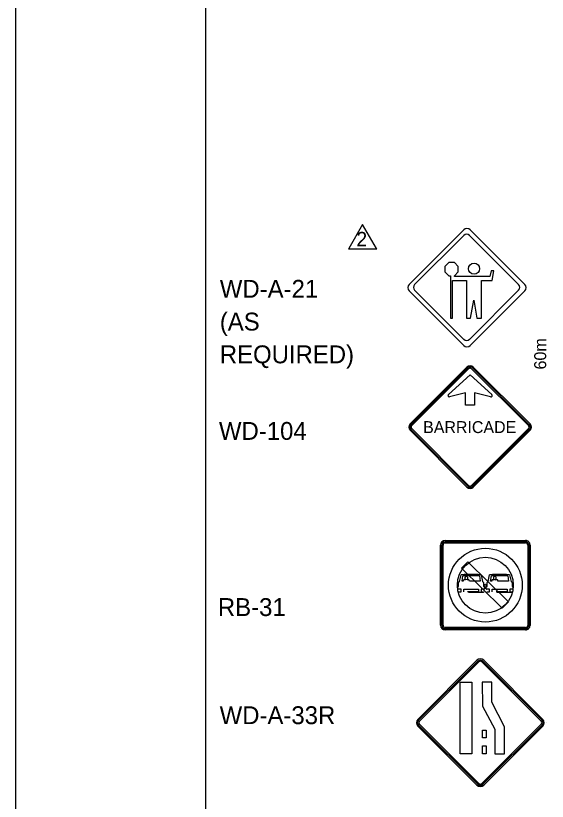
# Model space of a CAD drawing. Extents: x 1056 to 1280, y 240 to 519.
# Drawn here: x 1055.6 to 1109, y 308.9 to 388 of the extents above; entities that cross this region are included whole.
import ezdxf

# ---------------------------------------------------------------- set-up
doc = ezdxf.new("R2010")
doc.units = 0
for name, color, linetype in [('Level 1', 7, 'Continuous'), ('Level 10', 7, 'Continuous'), ('Level 17', 7, 'Continuous'), ('Level 29', 7, 'Continuous'), ('Level 44', 7, 'Continuous')]:
    doc.layers.add(name, color=color, linetype=linetype)

msp = doc.modelspace()

# ---------------------------------------------------------------- linework, layer by layer
at = {"layer": 'Level 1'}
for p, q in [((1099.137, 363.179), (1098.743, 362.785)), ((1099.694, 363.179), (1099.137, 363.179)), ((1100.088, 362.785), (1099.694, 363.179)), ((1098.743, 362.785), (1098.743, 362.228)), ((1100.088, 362.228), (1100.088, 362.785)), ((1103.408, 362.36), (1103.264, 361.761)), ((1103.658, 362.36), (1103.408, 362.36)), ((1103.495, 361.359), (1103.658, 362.36)), ((1098.743, 362.228), (1099.137, 361.834)), ((1099.137, 361.834), (1099.315, 361.834)), ((1099.315, 361.834), (1099.315, 357.568)), ((1099.694, 361.834), (1100.088, 362.228)), ((1099.694, 361.761), (1099.694, 361.834)), ((1103.264, 361.761), (1099.694, 361.761)), ((1099.511, 357.568), (1099.511, 361.359)), ((1099.511, 361.359), (1100.931, 361.359)), ((1100.931, 361.359), (1100.931, 357.568)), ((1102.419, 357.568), (1102.419, 361.359)), ((1102.419, 361.359), (1103.495, 361.359)), ((1101.307, 357.568), (1101.644, 359.384)), ((1101.644, 359.384), (1101.961, 357.568)), ((1099.315, 357.568), (1099.511, 357.568)), ((1100.931, 357.568), (1101.307, 357.568)), ((1101.961, 357.568), (1102.419, 357.568))]:
    msp.add_line(p, q, dxfattribs=at)
msp.add_circle((1101.68, 362.56), 0.559, dxfattribs=at)
at = {"layer": 'Level 10'}
for points in [[(1055.562, 518.817), (1271.562, 518.817), (1271.562, 239.817), (1055.562, 239.817)], [(1074.688, 508.008), (1261.562, 508.008), (1261.562, 250.626), (1074.688, 250.626)]]:
    msp.add_lwpolyline(points, close=True, dxfattribs=at)
at = {"layer": 'Level 17'}
for p, q in [((1095.234, 346.927), (1100.953, 352.646)), ((1095.319, 346.842), (1101.038, 352.562)), ((1095.404, 346.758), (1101.123, 352.477)), ((1101.428, 352.477), (1107.148, 346.758)), ((1101.513, 352.562), (1107.232, 346.842)), ((1101.598, 352.646), (1107.317, 346.927)), ((1099.212, 349.644), (1099.212, 349.644)), ((1099.212, 349.644), (1099.212, 349.644)), ((1099.212, 349.644), (1099.212, 349.644)), ((1094.912, 346.605), (1094.912, 346.605)), ((1100.953, 340.563), (1095.234, 346.282)), ((1101.038, 340.648), (1095.319, 346.367)), ((1101.123, 340.733), (1095.404, 346.452)), ((1107.148, 346.452), (1101.428, 340.733)), ((1107.232, 346.367), (1101.513, 340.648)), ((1107.317, 346.282), (1101.598, 340.563)), ((1098.311, 326.645), (1098.311, 334.724)), ((1098.431, 326.645), (1098.431, 334.724)), ((1098.551, 326.645), (1098.551, 334.724)), ((1098.768, 335.181), (1106.852, 335.185)), ((1098.768, 335.061), (1106.852, 335.065)), ((1098.768, 334.941), (1106.852, 334.946)), ((1107.07, 334.729), (1107.069, 326.639)), ((1107.19, 334.729), (1107.189, 326.639)), ((1107.31, 334.729), (1107.309, 326.639)), ((1100.226, 331.041), (1100.376, 331.723)), ((1100.468, 331.104), (1100.554, 331.627)), ((1100.593, 331.667), (1102.162, 331.667)), ((1102.209, 331.627), (1102.289, 331.104)), ((1102.381, 331.723), (1102.531, 331.041)), ((1103.092, 331.041), (1103.242, 331.723)), ((1103.334, 331.104), (1103.42, 331.627)), ((1103.459, 331.667), (1105.028, 331.667)), ((1105.074, 331.627), (1105.155, 331.104)), ((1105.247, 331.723), (1105.397, 331.041)), ((1100.124, 330.971), (1100.227, 331.041)), ((1100.124, 330.552), (1100.124, 330.971)), ((1100.582, 331.104), (1100.468, 331.104)), ((1100.589, 331.173), (1100.582, 331.104)), ((1100.808, 331.224), (1100.635, 331.213)), ((1100.819, 331.287), (1100.819, 331.235)), ((1100.969, 331.235), (1100.969, 331.287)), ((1101.158, 331.213), (1100.985, 331.224)), ((1101.208, 331.104), (1101.197, 331.173)), ((1102.289, 331.104), (1101.208, 331.104)), ((1102.531, 331.041), (1102.634, 330.971)), ((1102.634, 330.971), (1102.634, 330.552)), ((1102.99, 330.971), (1103.093, 331.041)), ((1102.99, 330.552), (1102.99, 330.971)), ((1103.448, 331.104), (1103.334, 331.104)), ((1103.454, 331.173), (1103.448, 331.104)), ((1103.674, 331.224), (1103.501, 331.213)), ((1103.684, 331.287), (1103.684, 331.235)), ((1103.834, 331.235), (1103.834, 331.287)), ((1104.023, 331.213), (1103.851, 331.224)), ((1104.074, 331.104), (1104.063, 331.173)), ((1105.155, 331.104), (1104.074, 331.104)), ((1105.397, 331.041), (1105.499, 330.971)), ((1105.499, 330.971), (1105.499, 330.552)), ((1100.033, 330.329), (1100.033, 330.506)), ((1100.079, 330.552), (1100.124, 330.552)), ((1100.366, 330.282), (1100.079, 330.282)), ((1100.142, 329.937), (1100.142, 330.012)), ((1100.142, 330.012), (1100.366, 330.012)), ((1100.366, 330.012), (1100.366, 330.282)), ((1100.631, 330.012), (1100.631, 330.282)), ((1100.631, 330.282), (1102.128, 330.282)), ((1102.128, 330.012), (1101.031, 330.012)), ((1102.616, 329.937), (1101.106, 329.937)), ((1102.128, 330.282), (1102.128, 330.012)), ((1102.679, 330.282), (1102.392, 330.282)), ((1102.392, 330.282), (1102.392, 330.012)), ((1102.392, 330.012), (1102.616, 330.012)), ((1102.616, 330.012), (1102.616, 329.937)), ((1102.634, 330.552), (1102.679, 330.552)), ((1102.725, 330.506), (1102.725, 330.329)), ((1102.898, 330.329), (1102.898, 330.506)), ((1102.945, 330.552), (1102.99, 330.552)), ((1103.232, 330.282), (1102.945, 330.282)), ((1103.007, 329.937), (1103.007, 330.012)), ((1103.007, 330.012), (1103.232, 330.012)), ((1103.232, 330.012), (1103.232, 330.282)), ((1103.496, 330.012), (1103.496, 330.282)), ((1103.496, 330.282), (1104.993, 330.282)), ((1104.993, 330.012), (1103.897, 330.012)), ((1105.482, 329.937), (1103.971, 329.937)), ((1104.993, 330.282), (1104.993, 330.012)), ((1105.545, 330.282), (1105.258, 330.282)), ((1105.258, 330.282), (1105.258, 330.012)), ((1105.258, 330.012), (1105.482, 330.012)), ((1105.482, 330.012), (1105.482, 329.937)), ((1105.499, 330.552), (1105.545, 330.552)), ((1105.591, 330.506), (1105.591, 330.329)), ((1098.311, 326.189), (1098.311, 326.189)), ((1098.311, 326.189), (1098.311, 326.189)), ((1106.853, 326.423), (1098.768, 326.428)), ((1106.853, 326.303), (1098.768, 326.308)), ((1106.853, 326.183), (1098.768, 326.188)), ((1096.012, 317.172), (1101.97, 323.13)), ((1096.101, 317.083), (1102.059, 323.041)), ((1096.19, 316.996), (1102.148, 322.952)), ((1102.465, 322.952), (1108.422, 316.996)), ((1102.554, 323.041), (1108.511, 317.083)), ((1102.642, 323.13), (1108.6, 317.172)), ((1101.97, 310.543), (1096.012, 316.501)), ((1102.059, 310.631), (1096.101, 316.588)), ((1102.148, 310.72), (1096.19, 316.677)), ((1108.422, 316.677), (1102.465, 310.72)), ((1108.511, 316.588), (1102.554, 310.631)), ((1108.6, 316.501), (1102.642, 310.543)), ((1108.935, 316.836), (1108.935, 316.836))]:
    msp.add_line(p, q, dxfattribs=at)
for points in [[(1099.089, 349.878), (1101.276, 351.866), (1103.463, 349.878)], [(1099.089, 349.878), (1101.276, 351.866), (1103.463, 349.878)], [(1099.089, 349.878), (1101.276, 351.866), (1103.463, 349.878)], [(1103.334, 349.644), (1101.727, 350.056), (1101.727, 348.806), (1100.82, 348.806), (1100.82, 350.056), (1099.212, 349.644)], [(1103.334, 349.644), (1101.727, 350.056), (1101.727, 348.806), (1100.82, 348.806), (1100.82, 350.056), (1099.212, 349.644)], [(1103.334, 349.644), (1101.727, 350.056), (1101.727, 348.806), (1100.82, 348.806), (1100.82, 350.056), (1099.212, 349.644)]]:
    msp.add_lwpolyline(points, dxfattribs=at)
for points in [[(1101.039, 333.029), (1105.138, 329.004), (1104.503, 328.368), (1100.405, 332.393)], [(1100.266, 320.928), (1101.438, 320.928), (1101.438, 313.688), (1100.266, 313.688)], [(1102.492, 320.928), (1102.508, 318.517), (1103.756, 316.193), (1103.756, 313.688), (1104.731, 313.688), (1104.731, 316.433), (1103.466, 318.907), (1103.466, 320.928)], [(1102.508, 316.098), (1102.898, 316.098), (1102.898, 315.296), (1102.508, 315.296)], [(1102.508, 314.492), (1102.898, 314.492), (1102.898, 313.688), (1102.508, 313.688)]]:
    msp.add_lwpolyline(points, close=True, dxfattribs=at)
for radius in [3.715, 2.811, 0.109]:
    msp.add_circle((1102.812, 330.685), radius, dxfattribs=at)
for centre, radius, start, end in [((1101.276, 352.323), 0.456, 45, 135), ((1101.276, 352.323), 0.336, 45, 135), ((1101.276, 352.323), 0.216, 45, 135), ((1099.18, 349.774), 0.137, 132.30479, 284.40748), ((1099.18, 349.774), 0.137, 132.30479, 284.40748), ((1099.18, 349.774), 0.137, 132.30479, 284.40748), ((1103.369, 349.774), 0.137, 255.59252, 47.69521), ((1103.369, 349.774), 0.137, 255.59252, 47.69521), ((1103.369, 349.774), 0.137, 255.59252, 47.69521), ((1095.557, 346.604), 0.456, 135, 225), ((1095.557, 346.604), 0.336, 135, 225), ((1095.557, 346.604), 0.216, 135, 225), ((1106.995, 346.604), 0.216, 315, 45), ((1106.995, 346.604), 0.336, 315, 45), ((1106.995, 346.604), 0.456, 315, 45), ((1101.276, 340.885), 0.456, 225, 315), ((1101.276, 340.885), 0.336, 225, 315), ((1101.276, 340.885), 0.216, 225, 315), ((1098.769, 334.724), 0.457, 90.03529, 179.99948), ((1098.769, 334.724), 0.337, 90.03529, 179.99948), ((1098.769, 334.724), 0.217, 90.03529, 179.99948), ((1106.853, 334.729), 0.457, 0, 90.03486), ((1106.853, 334.729), 0.337, 0, 90.03486), ((1106.853, 334.729), 0.217, 0, 90.03486), ((1100.596, 331.62), 0.0448, 90, 170.90972), ((1100.897, 331.424), 0.149, 302.76657, 235.94147), ((1102.163, 331.62), 0.0448, 9.09028, 90), ((1103.462, 331.62), 0.0448, 90, 170.90972), ((1103.763, 331.424), 0.149, 302.76657, 235.94147), ((1105.029, 331.62), 0.0448, 9.09028, 90), ((1100.636, 331.167), 0.0448, 93.82218, 171.86989), ((1100.806, 331.238), 0.0149, 273.79849, 0), ((1100.806, 331.287), 0.015, 0, 60.10537), ((1100.985, 331.285), 0.0149, 119.13929, 180), ((1100.985, 331.238), 0.0149, 180, 266.20151), ((1101.155, 331.167), 0.0448, 8.11866, 86.21836), ((1103.502, 331.167), 0.0448, 93.82218, 171.86989), ((1103.672, 331.238), 0.0149, 273.79849, 0), ((1103.672, 331.287), 0.015, 0, 60.10537), ((1103.851, 331.285), 0.0149, 119.13929, 180), ((1103.851, 331.238), 0.0149, 180, 266.20151), ((1104.021, 331.167), 0.0448, 8.11866, 86.21836), ((1100.08, 330.508), 0.0448, 90.00001, 180.00001), ((1100.08, 330.328), 0.0448, 180.00001, 270), ((1102.679, 330.508), 0.0448, 359.99999, 89.99999), ((1102.679, 330.328), 0.0448, 270, 359.99999), ((1102.946, 330.508), 0.0448, 90.00001, 180.00001), ((1102.946, 330.328), 0.0448, 180.00001, 270), ((1105.545, 330.508), 0.0448, 359.99999, 89.99999), ((1105.545, 330.328), 0.0448, 270, 359.99999), ((1098.769, 326.645), 0.457, 180, 269.96489), ((1098.769, 326.645), 0.337, 180, 269.96489), ((1098.769, 326.645), 0.217, 180, 269.96489), ((1106.853, 326.64), 0.457, 269.96512, 0), ((1106.853, 326.64), 0.337, 269.96512, 0), ((1106.853, 326.64), 0.217, 269.96512, 0), ((1102.306, 322.793), 0.475, 45, 135), ((1102.306, 322.793), 0.35, 45, 135), ((1102.306, 322.793), 0.225, 45, 135), ((1096.348, 316.836), 0.475, 135, 225), ((1096.348, 316.836), 0.35, 135, 225), ((1096.348, 316.836), 0.225, 135, 225), ((1108.263, 316.836), 0.225, 315, 45), ((1108.263, 316.836), 0.35, 315, 45), ((1108.263, 316.836), 0.475, 315, 45), ((1102.306, 310.879), 0.475, 225, 315), ((1102.306, 310.879), 0.35, 225, 315), ((1102.306, 310.879), 0.225, 225, 315)]:
    msp.add_arc(centre, radius, start, end, dxfattribs=at)
for centre in [(1101.38, 331.725), (1104.245, 331.725)]:
    msp.add_ellipse(centre, major_axis=(-1.001, 0), ratio=0.04642, start_param=3.141593, end_param=6.283185, dxfattribs=at)
at = {"layer": 'Level 29'}
for points in [[(1090.467, 367.02), (1089.074, 364.595)], [(1091.861, 364.595), (1090.467, 367.02)], [(1089.074, 364.595), (1089.048, 364.55), (1091.887, 364.55), (1091.861, 364.595)]]:
    msp.add_lwpolyline(points, dxfattribs=at)
at = {"layer": 'Level 44'}
for p, q in [((1100.638, 366.462), (1095.144, 360.976)), ((1106.772, 360.976), (1101.288, 366.462)), ((1095.694, 360.972), (1100.638, 365.91)), ((1101.222, 365.91), (1106.16, 360.972)), ((1095.144, 360.326), (1100.638, 354.834)), ((1095.15, 360.326), (1095.144, 360.326)), ((1100.638, 355.446), (1095.694, 360.386)), ((1106.16, 360.386), (1101.222, 355.446)), ((1101.288, 354.834), (1106.772, 360.326))]:
    msp.add_line(p, q, dxfattribs=at)
for centre, radius, start, end in [((1100.962, 366.139), 0.459, 45, 135), ((1100.929, 365.618), 0.413, 45, 135), ((1095.473, 360.65), 0.459, 135, 224.99999), ((1095.99, 360.678), 0.413, 135, 224.99999), ((1105.869, 360.678), 0.413, 315, 45), ((1106.45, 360.65), 0.459, 315, 45), ((1100.929, 355.739), 0.413, 225, 315), ((1100.962, 355.162), 0.459, 225, 315)]:
    msp.add_arc(centre, radius, start, end, dxfattribs=at)

# ---------------------------------------------------------------- texts
at = {"layer": 'Level 10'}
msp.add_text('2', height=1.448, rotation=360, dxfattribs=at).set_placement((1089.84, 364.819))
for s, p in [('WD-A-21', (1076.095, 359.634)), ('WD-A-21', (1076.095, 359.634)), ('(AS ', (1076.095, 356.334)), ('(AS ', (1076.095, 356.334)), ('REQUIRED)', (1076.095, 353.034)), ('REQUIRED)', (1076.095, 353.034)), ('WD-104', (1076.008, 345.322)), ('RB-31', (1075.903, 327.58)), ('WD-A-33R', (1076.078, 316.691))]:
    msp.add_text(s, height=1.8, dxfattribs=at).set_placement(p)
at = {"layer": 'Level 17'}
msp.add_text('BARRICADE', height=1.2, dxfattribs=at).set_placement((1096.554, 346.005))
at = {"layer": 'Level 44'}
msp.add_text('60m', height=1.2095, rotation=90, dxfattribs=at).set_placement((1108.936, 352.408))

doc.saveas('drawing.dxf')
